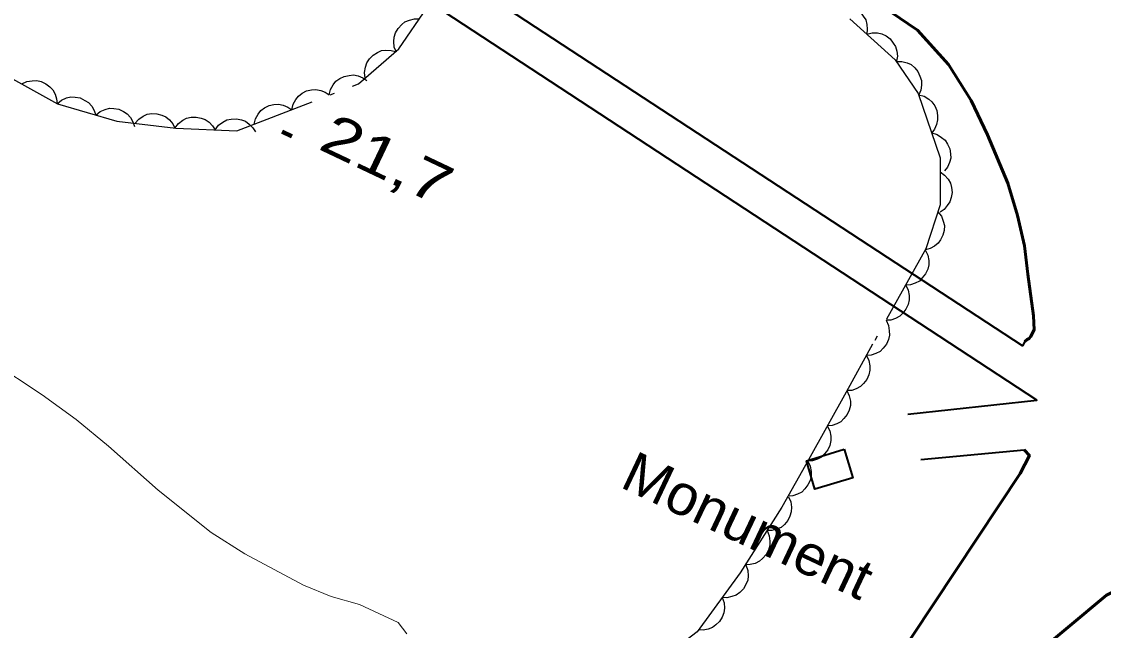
# Model space of a CAD drawing. Extents: x 356765 to 358572, y 5103174 to 5104650.
# Drawn here: x 357207.62 to 357247.91, y 5103721.64 to 5103744.31 of the extents above; entities that cross this region are included whole.
import ezdxf

# ---------------------------------------------------------------- set-up
doc = ezdxf.new("R2010")
doc.units = 0
doc.header["$LTSCALE"] = 0.6
doc.linetypes.add('DOT_DASHED', pattern=[7.7, 5, -1.2, 0.3, -1.2])
for name, color, linetype, lineweight in [('2', 7, 'Continuous', 13), ('21', 7, 'Continuous', 53), ('22', 7, 'Continuous', 35), ('3', 7, 'Continuous', 140), ('39', 7, 'Continuous', 35), ('44', 7, 'Continuous', 25)]:
    doc.layers.add(name, color=color, linetype=linetype, lineweight=lineweight)

msp = doc.modelspace()

# ---------------------------------------------------------------- linework, layer by layer
at = {"layer": '2'}
msp.add_lwpolyline([(357221.97, 5103721.51), (357221.65, 5103721.94), (357220.21, 5103722.61), (357219.15, 5103722.91), (357218.12, 5103723.33), (357215.94, 5103724.5), (357214.68, 5103725.29), (357212.7, 5103726.86), (357210.86, 5103728.5), (357209.65, 5103729.5), (357208.39, 5103730.42), (357206.5, 5103731.65)], dxfattribs=at)
at = {"layer": '21'}
for points in [[(357195.84, 5103777.59), (357203.05, 5103770.32), (357205.66, 5103768.28), (357209.77, 5103765.28), (357213.62, 5103762.65), (357220.27, 5103758.23), (357223.48, 5103755.9), (357227.34, 5103753.12), (357238.49, 5103745.72), (357239.98, 5103744.68), (357240.99, 5103743.99), (357242.15, 5103742.72), (357242.99, 5103741.38), (357243.6, 5103740.09), (357244.35, 5103738.3), (357244.72, 5103737.09), (357244.97, 5103735.96), (357245.1, 5103734.91), (357245.31, 5103733.36), (357245.34, 5103732.84), (357245.2, 5103732.58), (357245.15, 5103732.51), (357245.08, 5103732.48), (357244.99, 5103732.4)], [(357244.96, 5103728.37), (357245.16, 5103728.16), (357244.81, 5103727.48), (357232.73, 5103709.28)], [(357234.72, 5103707.75), (357240.88, 5103716.19), (357242.95, 5103718.51), (357243.47, 5103719.09), (357244.26, 5103719.81), (357245.17, 5103720.57), (357248.03, 5103722.95), (357249.24, 5103723.54), (357252.99, 5103725.42)]]:
    msp.add_lwpolyline(points, dxfattribs=at)
at = {"layer": '22'}
msp.add_line((357241.12, 5103728.01), (357244.96, 5103728.37), dxfattribs=at)
for points in [[(357244.99, 5103732.4), (357244.9, 5103732.24), (357218.68, 5103749.41)], [(357240.63, 5103729.7), (357245.44, 5103730.22), (357217.92, 5103748.25)]]:
    msp.add_lwpolyline(points, dxfattribs=at)
at = {"layer": '3'}
msp.add_line((357217.32, 5103740.22), (357217.68, 5103740.05), dxfattribs=at)
at = {"layer": '39'}
msp.add_lwpolyline([(357238.26, 5103728.39), (357238.58, 5103727.33), (357237.17, 5103726.9), (357236.85, 5103727.96), (357238.26, 5103728.39)], close=True, dxfattribs=at)
at = {"layer": '44', "linetype": 'DOT_DASHED'}
for points in [[(357207.17, 5103742.24), (357208.95, 5103741.25), (357211.17, 5103740.6), (357213.36, 5103740.35), (357215.64, 5103740.24), (357220.17, 5103742), (357221.67, 5103743.3), (357222.72, 5103744.84)], [(357238.47, 5103744.41), (357240.16, 5103742.89), (357241.02, 5103741.63), (357241.83, 5103739.24), (357241.83, 5103737.49), (357241.3, 5103735.85), (357239.32, 5103732.3), (357238.33, 5103730.52), (357236.93, 5103728), (357235.94, 5103726.23), (357234.39, 5103723.79), (357232.78, 5103721.59), (357230.73, 5103720.02), (357227.58, 5103719.25), (357225.13, 5103719.07), (357223.3, 5103718.92), (357221.75, 5103718.24), (357220.79, 5103717.22)]]:
    msp.add_lwpolyline(points, dxfattribs=at)
at = {"layer": '44'}
for points in [[(357237.98, 5103744.85), (357238.18, 5103744.9), (357238.39, 5103744.89), (357238.55, 5103744.86), (357238.71, 5103744.78), (357238.85, 5103744.67), (357238.97, 5103744.52), (357239.06, 5103744.38), (357239.1, 5103744.21), (357239.12, 5103744.03), (357239.1, 5103743.85)], [(357221.58, 5103743.17), (357221.5, 5103743.36), (357221.49, 5103743.57), (357221.5, 5103743.73), (357221.55, 5103743.9), (357221.64, 5103744.06), (357221.78, 5103744.2), (357221.9, 5103744.3), (357222.07, 5103744.37), (357222.25, 5103744.41), (357222.43, 5103744.41)], [(357239.1, 5103743.85), (357239.3, 5103743.9), (357239.5, 5103743.89), (357239.66, 5103743.86), (357239.82, 5103743.78), (357239.97, 5103743.67), (357240.09, 5103743.51), (357240.17, 5103743.38), (357240.22, 5103743.21), (357240.24, 5103743.02), (357240.21, 5103742.84)], [(357220.42, 5103742.21), (357220.39, 5103742.42), (357220.43, 5103742.62), (357220.48, 5103742.78), (357220.58, 5103742.92), (357220.71, 5103743.06), (357220.87, 5103743.16), (357221.02, 5103743.23), (357221.19, 5103743.25), (357221.38, 5103743.24), (357221.55, 5103743.2)], [(357240.2, 5103742.83), (357240.41, 5103742.83), (357240.6, 5103742.78), (357240.75, 5103742.71), (357240.89, 5103742.59), (357241, 5103742.45), (357241.08, 5103742.28), (357241.14, 5103742.12), (357241.14, 5103741.94), (357241.11, 5103741.76), (357241.04, 5103741.59)], [(357207.63, 5103741.99), (357207.81, 5103742.08), (357208.01, 5103742.11), (357208.18, 5103742.12), (357208.35, 5103742.08), (357208.52, 5103742), (357208.67, 5103741.88), (357208.78, 5103741.77), (357208.87, 5103741.61), (357208.92, 5103741.44), (357208.94, 5103741.26)], [(357219.08, 5103741.58), (357219.12, 5103741.78), (357219.22, 5103741.96), (357219.32, 5103742.09), (357219.47, 5103742.19), (357219.63, 5103742.27), (357219.82, 5103742.31), (357219.98, 5103742.33), (357220.15, 5103742.29), (357220.33, 5103742.22), (357220.48, 5103742.12)], [(357217.68, 5103741.03), (357217.73, 5103741.24), (357217.83, 5103741.41), (357217.93, 5103741.54), (357218.07, 5103741.65), (357218.23, 5103741.73), (357218.42, 5103741.77), (357218.58, 5103741.78), (357218.76, 5103741.75), (357218.93, 5103741.68), (357219.08, 5103741.58)], [(357241.03, 5103741.59), (357241.24, 5103741.53), (357241.41, 5103741.42), (357241.53, 5103741.32), (357241.63, 5103741.17), (357241.71, 5103741), (357241.74, 5103740.81), (357241.74, 5103740.65), (357241.7, 5103740.48), (357241.62, 5103740.31), (357241.52, 5103740.17)], [(357208.94, 5103741.25), (357209.1, 5103741.39), (357209.29, 5103741.47), (357209.45, 5103741.51), (357209.62, 5103741.5), (357209.8, 5103741.47), (357209.98, 5103741.38), (357210.11, 5103741.3), (357210.23, 5103741.16), (357210.32, 5103741), (357210.38, 5103740.83)], [(357216.28, 5103740.49), (357216.33, 5103740.69), (357216.43, 5103740.87), (357216.53, 5103741), (357216.67, 5103741.1), (357216.84, 5103741.19), (357217.02, 5103741.22), (357217.19, 5103741.24), (357217.36, 5103741.2), (357217.53, 5103741.13), (357217.68, 5103741.03)], [(357210.38, 5103740.83), (357210.54, 5103740.97), (357210.73, 5103741.04), (357210.89, 5103741.09), (357211.06, 5103741.08), (357211.24, 5103741.05), (357211.41, 5103740.96), (357211.55, 5103740.88), (357211.67, 5103740.74), (357211.76, 5103740.58), (357211.82, 5103740.41)], [(357211.84, 5103740.52), (357211.98, 5103740.68), (357212.15, 5103740.79), (357212.3, 5103740.86), (357212.47, 5103740.89), (357212.66, 5103740.88), (357212.84, 5103740.83), (357212.99, 5103740.77), (357213.13, 5103740.65), (357213.25, 5103740.51), (357213.33, 5103740.35)], [(357213.33, 5103740.35), (357213.46, 5103740.52), (357213.62, 5103740.64), (357213.76, 5103740.72), (357213.94, 5103740.75), (357214.12, 5103740.76), (357214.31, 5103740.72), (357214.46, 5103740.67), (357214.6, 5103740.57), (357214.73, 5103740.43), (357214.83, 5103740.28)], [(357214.83, 5103740.28), (357214.95, 5103740.45), (357215.12, 5103740.57), (357215.26, 5103740.65), (357215.43, 5103740.68), (357215.62, 5103740.69), (357215.81, 5103740.65), (357215.96, 5103740.6), (357216.1, 5103740.49), (357216.23, 5103740.36), (357216.33, 5103740.21)], [(357241.52, 5103740.17), (357241.72, 5103740.11), (357241.89, 5103740), (357242.02, 5103739.9), (357242.11, 5103739.75), (357242.19, 5103739.58), (357242.22, 5103739.39), (357242.23, 5103739.23), (357242.18, 5103739.06), (357242.11, 5103738.89), (357242, 5103738.75)], [(357241.83, 5103738.72), (357242, 5103738.6), (357242.13, 5103738.44), (357242.22, 5103738.3), (357242.26, 5103738.13), (357242.28, 5103737.95), (357242.25, 5103737.76), (357242.2, 5103737.6), (357242.1, 5103737.46), (357241.98, 5103737.32), (357241.83, 5103737.22)], [(357241.75, 5103737.23), (357241.88, 5103737.07), (357241.95, 5103736.88), (357241.99, 5103736.72), (357241.98, 5103736.54), (357241.94, 5103736.36), (357241.85, 5103736.19), (357241.76, 5103736.06), (357241.62, 5103735.95), (357241.46, 5103735.86), (357241.29, 5103735.81)], [(357241.28, 5103735.81), (357241.37, 5103735.62), (357241.41, 5103735.42), (357241.41, 5103735.26), (357241.37, 5103735.09), (357241.29, 5103734.92), (357241.17, 5103734.77), (357241.06, 5103734.65), (357240.9, 5103734.57), (357240.73, 5103734.51), (357240.55, 5103734.5)], [(357240.55, 5103734.5), (357240.64, 5103734.31), (357240.68, 5103734.11), (357240.68, 5103733.95), (357240.64, 5103733.78), (357240.56, 5103733.61), (357240.44, 5103733.46), (357240.33, 5103733.34), (357240.17, 5103733.26), (357240, 5103733.2), (357239.82, 5103733.19)], [(357239.82, 5103733.19), (357239.91, 5103733), (357239.94, 5103732.8), (357239.95, 5103732.64), (357239.91, 5103732.47), (357239.83, 5103732.3), (357239.71, 5103732.15), (357239.6, 5103732.03), (357239.44, 5103731.95), (357239.26, 5103731.89), (357239.09, 5103731.88)], [(357239.09, 5103731.88), (357239.18, 5103731.69), (357239.22, 5103731.49), (357239.22, 5103731.33), (357239.18, 5103731.16), (357239.1, 5103730.99), (357238.98, 5103730.84), (357238.87, 5103730.72), (357238.71, 5103730.64), (357238.54, 5103730.58), (357238.36, 5103730.57)], [(357238.36, 5103730.57), (357238.45, 5103730.38), (357238.49, 5103730.18), (357238.49, 5103730.02), (357238.45, 5103729.85), (357238.37, 5103729.68), (357238.25, 5103729.53), (357238.14, 5103729.41), (357237.98, 5103729.33), (357237.81, 5103729.27), (357237.63, 5103729.26)], [(357237.63, 5103729.26), (357237.72, 5103729.07), (357237.76, 5103728.87), (357237.76, 5103728.71), (357237.72, 5103728.53), (357237.65, 5103728.37), (357237.53, 5103728.22), (357237.41, 5103728.1), (357237.26, 5103728.02), (357237.08, 5103727.96), (357236.9, 5103727.95)], [(357236.9, 5103727.95), (357236.99, 5103727.76), (357237.03, 5103727.56), (357237.03, 5103727.39), (357236.99, 5103727.22), (357236.91, 5103727.06), (357236.79, 5103726.91), (357236.68, 5103726.79), (357236.52, 5103726.71), (357236.35, 5103726.65), (357236.17, 5103726.64)], [(357236.19, 5103726.62), (357236.27, 5103726.43), (357236.3, 5103726.23), (357236.29, 5103726.06), (357236.24, 5103725.9), (357236.16, 5103725.73), (357236.03, 5103725.59), (357235.91, 5103725.48), (357235.74, 5103725.41), (357235.57, 5103725.36), (357235.39, 5103725.36)], [(357235.39, 5103725.36), (357235.47, 5103725.17), (357235.49, 5103724.96), (357235.49, 5103724.8), (357235.44, 5103724.63), (357235.35, 5103724.47), (357235.22, 5103724.32), (357235.1, 5103724.22), (357234.94, 5103724.14), (357234.76, 5103724.1), (357234.58, 5103724.09)], [(357234.6, 5103724.08), (357234.67, 5103723.88), (357234.68, 5103723.68), (357234.67, 5103723.51), (357234.6, 5103723.35), (357234.51, 5103723.19), (357234.37, 5103723.06), (357234.24, 5103722.96), (357234.08, 5103722.9), (357233.89, 5103722.86), (357233.71, 5103722.87)], [(357233.71, 5103722.87), (357233.79, 5103722.67), (357233.8, 5103722.47), (357233.78, 5103722.3), (357233.72, 5103722.14), (357233.62, 5103721.98), (357233.48, 5103721.85), (357233.36, 5103721.75), (357233.19, 5103721.69), (357233.01, 5103721.65), (357232.83, 5103721.66)]]:
    msp.add_lwpolyline(points, dxfattribs=at)

# ---------------------------------------------------------------- texts
at = {"layer": '3', "width": 1.3}
msp.add_text('21,7   ', height=1.5, rotation=334.619, dxfattribs=at).set_placement((357218.62, 5103739.59))
at = {"layer": '39', "width": 1.05}
msp.add_text('Monument', height=1.5, rotation=334.72, dxfattribs=at).set_placement((357229.86, 5103727))

doc.saveas('drawing.dxf')
